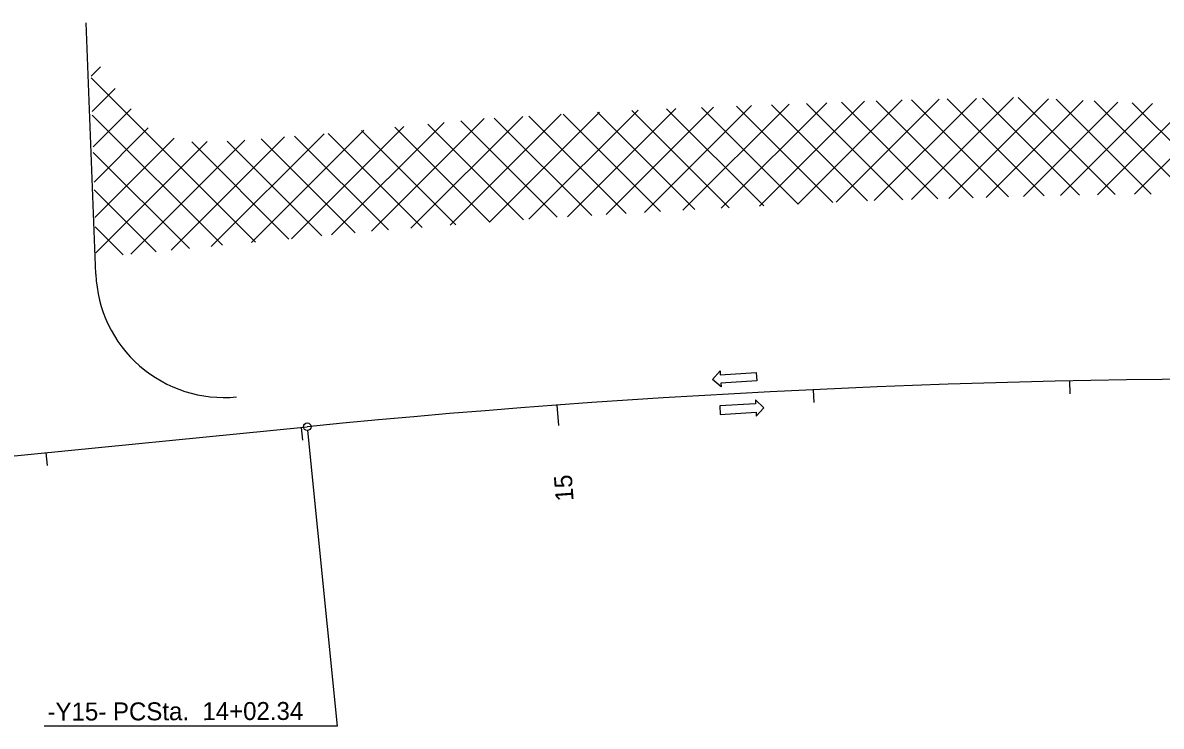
# Model space of a CAD drawing. Extents: x 2389694 to 2405615, y 546931 to 573532.
# Drawn here: x 2396738.8 to 2397182.4, y 552445.3 to 552719.6 of the extents above; entities that cross this region are included whole.
import ezdxf

# ---------------------------------------------------------------- set-up
doc = ezdxf.new("R2010")
doc.units = 0
for name, color, linetype in [('Prop EOT', 7, 'Continuous'), ('Prop Hatching', 7, 'Continuous'), ('Prop Horizontal Alignment', 7, 'Continuous'), ('Prop Horizontal Alignment Curve and Spiral Data', 7, 'Continuous'), ('Prop Horizontal Alignment Tick Large', 7, 'Continuous'), ('Prop Horizontal Alignment Tick Small', 7, 'Continuous'), ('Prop Lane Arrow Through CELL', 7, 'Continuous')]:
    doc.layers.add(name, color=color, linetype=linetype)

msp = doc.modelspace()

# ---------------------------------------------------------------- linework, layer by layer
at = {"layer": 'Prop EOT'}
msp.add_line((2396767.27, 552621.56), (2396763.54, 552719.61), dxfattribs=at)
msp.add_arc((2396817.23, 552623.46), 50, 182.1785, 275.5074, dxfattribs=at)
at = {"layer": 'Prop Hatching'}
for p, q in [((2396765.42, 552698.73), (2396769.11, 552702.42)), ((2396829.51, 552634.06), (2396765.44, 552698.12)), ((2396765.8, 552684.96), (2396774.76, 552693.93)), ((2396966.06, 552644.81), (2397007.98, 552686.73)), ((2396981.04, 552645.64), (2397022.69, 552687.29)), ((2396996.01, 552646.47), (2397037.4, 552687.86)), ((2397041, 552648.84), (2397003.29, 552686.55)), ((2397010.98, 552647.3), (2397052.1, 552688.43)), ((2397054.46, 552649.52), (2397016.91, 552687.07)), ((2397025.9, 552648.08), (2397066.81, 552688.99)), ((2397067.92, 552650.2), (2397030.53, 552687.6)), ((2397040.79, 552648.83), (2397081.49, 552689.53)), ((2397081.66, 552650.6), (2397044.14, 552688.12)), ((2397055.69, 552649.58), (2397095.94, 552689.83)), ((2397095.42, 552650.99), (2397057.76, 552688.64)), ((2397070.54, 552650.29), (2397110.38, 552690.13)), ((2397109.17, 552651.37), (2397071.38, 552689.17)), ((2397085.09, 552650.7), (2397124.82, 552690.43)), ((2397122.95, 552651.74), (2397085.09, 552689.6)), ((2397136.79, 552652.05), (2397098.94, 552689.89)), ((2397099.64, 552651.11), (2397138.44, 552689.91)), ((2397150.62, 552652.35), (2397112.79, 552690.18)), ((2397114.19, 552651.51), (2397151.97, 552689.29)), ((2397164.46, 552652.66), (2397126.67, 552690.44)), ((2397128.68, 552651.87), (2397165.49, 552688.68)), ((2397178.5, 552652.76), (2397141.49, 552689.77)), ((2397143.14, 552652.19), (2397179.02, 552688.06)), ((2397192.54, 552652.86), (2397156.3, 552689.1)), ((2397157.61, 552652.51), (2397192.79, 552687.69)), ((2397206.67, 552652.87), (2397171.12, 552688.42)), ((2397171.96, 552652.72), (2397206.56, 552687.32)), ((2396816.59, 552632.84), (2396765.84, 552683.58)), ((2396766.17, 552671.2), (2396781.05, 552686.08)), ((2396874.69, 552638.3), (2396918.62, 552682.22)), ((2396890.01, 552639.47), (2396933.61, 552683.07)), ((2396905.32, 552640.64), (2396948.59, 552683.91)), ((2396920.63, 552641.81), (2396963.57, 552684.74)), ((2396960.48, 552644.5), (2396922.54, 552682.45)), ((2396973.88, 552645.25), (2396935.93, 552683.2)), ((2396935.94, 552642.98), (2396978.55, 552685.58)), ((2396987.28, 552645.99), (2396949.32, 552683.95)), ((2396951.09, 552643.98), (2396993.27, 552686.16)), ((2397000.68, 552646.73), (2396962.71, 552684.7)), ((2397014.08, 552647.47), (2396976.11, 552685.45)), ((2397027.53, 552648.16), (2396989.67, 552686.02)), ((2396766.55, 552657.43), (2396787.69, 552678.57)), ((2396827.88, 552633.9), (2396871.63, 552677.66)), ((2396843.5, 552635.38), (2396887.29, 552679.18)), ((2396859.12, 552636.86), (2396902.96, 552680.7)), ((2396907.6, 552640.81), (2396870.84, 552677.58)), ((2396920.74, 552641.82), (2396883.73, 552678.83)), ((2396933.88, 552642.82), (2396896.62, 552680.08)), ((2396947.08, 552643.76), (2396909.51, 552681.34)), ((2396766.92, 552643.66), (2396797.84, 552674.58)), ((2396767.3, 552629.89), (2396810.66, 552673.26)), ((2396780.89, 552629.34), (2396825.38, 552673.84)), ((2396796.57, 552630.88), (2396840.78, 552675.1)), ((2396842.42, 552635.28), (2396804.6, 552673.11)), ((2396812.25, 552632.42), (2396856.18, 552676.35)), ((2396855.34, 552636.5), (2396818.4, 552673.45)), ((2396868.26, 552637.73), (2396831.64, 552674.35)), ((2396881.33, 552638.8), (2396844.71, 552675.42)), ((2396894.47, 552639.81), (2396857.79, 552676.48)), ((2396803.7, 552631.58), (2396766.23, 552669.05)), ((2396790.82, 552630.32), (2396766.63, 552654.51)), ((2396777.94, 552629.05), (2396767.02, 552639.97))]:
    msp.add_line(p, q, dxfattribs=at)
at = {"layer": 'Prop Horizontal Alignment'}
msp.add_line((2396449.28, 552522.14), (2396849.64, 552562.06), dxfattribs=at)
msp.add_arc((2397224.45, 548803.71), 3777, 82.19409, 95.69509, dxfattribs=at)
at = {"layer": 'Prop Horizontal Alignment Curve and Spiral Data'}
for p, q in [((2396849.79, 552560.57), (2396861.29, 552445.27)), ((2396861.29, 552445.27), (2396747.13, 552445.27))]:
    msp.add_line(p, q, dxfattribs=at)
msp.add_circle((2396849.64, 552562.06), 1.5, dxfattribs=at)
at = {"layer": 'Prop Horizontal Alignment Tick Large'}
msp.add_line((2396946.93, 552570.5), (2396947.52, 552562.52), dxfattribs=at)
at = {"layer": 'Prop Horizontal Alignment Tick Small'}
for p, q in [((2397146.68, 552579.91), (2397146.79, 552574.91)), ((2397046.74, 552576.52), (2397046.98, 552571.53)), ((2396847.31, 552561.83), (2396847.8, 552556.86)), ((2396747.8, 552551.91), (2396748.3, 552546.93))]:
    msp.add_line(p, q, dxfattribs=at)
at = {"layer": 'Prop Lane Arrow Through CELL'}
for p, q in [((2397007.55, 552580.48), (2397010.49, 552583.87)), ((2397010.89, 552577.58), (2397007.55, 552580.48)), ((2397010.49, 552583.87), (2397010.59, 552582.37)), ((2397010.59, 552582.37), (2397024.56, 552583.27)), ((2397024.77, 552579.98), (2397010.8, 552579.08)), ((2397024.56, 552583.27), (2397024.77, 552579.98)), ((2397010.8, 552579.08), (2397010.89, 552577.58)), ((2397027.59, 552569.5), (2397024.26, 552572.51)), ((2397024.26, 552572.51), (2397024.35, 552571.01)), ((2397024.35, 552571.01), (2397010.38, 552570.2)), ((2397010.38, 552570.2), (2397010.57, 552566.9)), ((2397010.57, 552566.9), (2397024.54, 552567.72)), ((2397024.54, 552567.72), (2397024.63, 552566.22)), ((2397024.63, 552566.22), (2397027.59, 552569.5))]:
    msp.add_line(p, q, dxfattribs=at)

# ---------------------------------------------------------------- texts
at = {"layer": 'Prop Horizontal Alignment Curve and Spiral Data'}
for s, rotation, p in [('15', 94.2137, (2396953.46, 552533.21)), ('-Y15- PCSta.  14+02.34', 0.1594, (2396748.44, 552447.47))]:
    msp.add_text(s, height=7, rotation=rotation, dxfattribs=at).set_placement(p)

doc.saveas('drawing.dxf')
